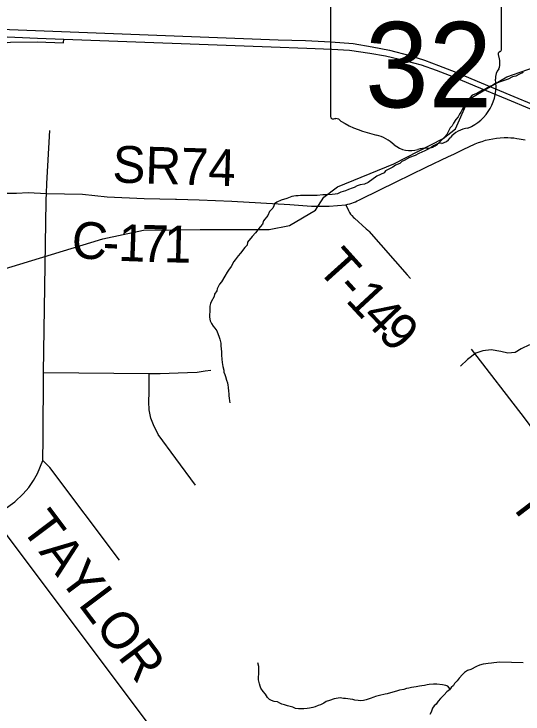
# Model space of a CAD drawing. Extents: x 0 to 34, y 0 to 22.
# Drawn here: x 3.321 to 4.106, y 16.889 to 17.969 of the extents above; entities that cross this region are included whole.
import ezdxf

# ---------------------------------------------------------------- set-up
doc = ezdxf.new("R2010")
doc.units = 0
for name, color, linetype in [('GM_X_County_Road', 7, 'Continuous'), ('GM_X_County_Road_Text', 7, 'Continuous'), ('GM_X_Interchange_Ramps', 7, 'Continuous'), ('GM_X_Minor_River', 7, 'Continuous'), ('GM_X_Rail_Line', 7, 'Continuous'), ('GM_X_State_Location', 7, 'Continuous'), ('GM_X_State_Route', 7, 'Continuous'), ('GM_X_State_Shield', 7, 'Continuous'), ('GM_X_Township_Road', 7, 'Continuous'), ('GM_X_Township_Road_Text', 7, 'Continuous')]:
    doc.layers.add(name, color=color, linetype=linetype)

msp = doc.modelspace()

# ---------------------------------------------------------------- linework, layer by layer
at = {"layer": 'GM_X_County_Road'}
for points in [[(4.0138, 17.7596), (4.032, 17.7682), (4.0373, 17.7704), (4.0428, 17.7723), (4.0483, 17.7739), (4.0539, 17.7753), (4.0595, 17.7764), (4.0652, 17.7772), (4.0709, 17.7778), (4.0767, 17.778), (4.0825, 17.7781), (4.0872, 17.7779), (4.092, 17.7775), (4.0967, 17.7769), (4.1001, 17.7764), (4.1034, 17.7758), (4.1092, 17.7745)], [(3.5715, 17.6829), (3.6063, 17.6822), (3.6566, 17.6798), (3.7464, 17.6747), (3.7797, 17.6723), (3.807, 17.6725), (3.8324, 17.6742), (3.8358, 17.6751), (3.8388, 17.6757), (3.8416, 17.6768), (3.8444, 17.6779), (3.8473, 17.6791), (3.8502, 17.6804), (3.8529, 17.6817), (3.8567, 17.6837), (3.9103, 17.7099), (3.9565, 17.7324), (3.991, 17.7487), (3.9993, 17.7527), (4.0138, 17.7596)], [(2.7634, 17.6374), (2.7985, 17.6331), (2.8242, 17.6342), (2.8636, 17.6377), (2.8914, 17.6399), (2.9314, 17.6429), (3.1876, 17.6772), (3.2242, 17.6821), (3.2631, 17.6869), (3.2961, 17.6924), (3.3246, 17.6924), (3.3425, 17.6933), (3.3709, 17.6917), (3.4263, 17.6906), (3.4641, 17.6869), (3.5212, 17.6842), (3.5695, 17.683), (3.5715, 17.6829)], [(3.7034, 16.6488), (3.5434, 16.8527), (3.3051, 17.1702), (3.2901, 17.1934)]]:
    msp.add_lwpolyline(points, dxfattribs=at)
at = {"layer": 'GM_X_Interchange_Ramps'}
msp.add_lwpolyline([(3.1029, 17.9047), (3.106, 17.9033), (3.1205, 17.8985), (3.1368, 17.8922), (3.1525, 17.8889), (3.167, 17.8879), (3.1832, 17.8902), (3.2012, 17.8958), (3.2205, 17.9034), (3.2348, 17.9089), (3.2473, 17.9137), (3.2605, 17.9165), (3.2756, 17.9199), (3.2939, 17.9235), (3.3149, 17.9256), (3.3561, 17.9261), (3.397, 17.9245), (3.3974, 17.93)], dxfattribs=at)
at = {"layer": 'GM_X_Minor_River'}
for points in [[(4.1062, 17.8785), (4.0997, 17.8756), (4.0951, 17.873), (4.0898, 17.8716), (4.0829, 17.8682), (4.0737, 17.8654), (4.0634, 17.8614), (4.0595, 17.8591), (4.0549, 17.8569), (4.0484, 17.8533), (4.0434, 17.8511), (4.0346, 17.8459), (4.0277, 17.8434), (4.0246, 17.84), (4.0223, 17.837), (4.0203, 17.8328), (4.0164, 17.8283), (4.0121, 17.8216), (4.0102, 17.8174), (4.0078, 17.8144), (4.0062, 17.8099), (4.0024, 17.8058), (3.9988, 17.8005), (3.9965, 17.796), (3.9938, 17.793), (3.9918, 17.7888)], [(3.9918, 17.7888), (3.9883, 17.7828), (3.9852, 17.7794), (3.9794, 17.7731), (3.9751, 17.769), (3.9678, 17.7653), (3.9644, 17.7627), (3.9575, 17.759), (3.9544, 17.7579), (3.9452, 17.7535), (3.9398, 17.7506), (3.931, 17.7473), (3.9226, 17.7425), (3.9191, 17.741), (3.9157, 17.7381), (3.9092, 17.7355), (3.9053, 17.7325), (3.9022, 17.7307), (3.8938, 17.7267), (3.8919, 17.7236), (3.8804, 17.7185), (3.8673, 17.7089), (3.8612, 17.7063), (3.8547, 17.7053), (3.8501, 17.7038), (3.8455, 17.7013), (3.8424, 17.6998), (3.8367, 17.698), (3.8321, 17.6958), (3.8248, 17.6936), (3.8195, 17.6914), (3.816, 17.6907), (3.8115, 17.6901), (3.8012, 17.6895), (3.797, 17.6896), (3.7882, 17.6889), (3.7841, 17.6886), (3.7746, 17.6888), (3.7628, 17.6886), (3.759, 17.6883), (3.7555, 17.688), (3.7494, 17.687), (3.7414, 17.6841), (3.733, 17.6815), (3.7261, 17.6786), (3.7223, 17.676), (3.7214, 17.6726), (3.7199, 17.6692), (3.7148, 17.664), (3.7121, 17.6579), (3.7055, 17.6497), (3.7042, 17.6444), (3.7004, 17.6403), (3.6934, 17.6309), (3.6883, 17.6253), (3.681, 17.6167), (3.6801, 17.6121), (3.6766, 17.6084), (3.67, 17.5997), (3.6662, 17.5956), (3.6619, 17.5896), (3.6595, 17.5866), (3.6556, 17.5791), (3.6513, 17.5734), (3.6494, 17.5704), (3.6459, 17.5644), (3.6408, 17.5557), (3.6377, 17.552), (3.6341, 17.5445), (3.6333, 17.5414), (3.6298, 17.5362), (3.6294, 17.5328), (3.6247, 17.5248), (3.6235, 17.5218), (3.6226, 17.5177), (3.6226, 17.5131), (3.6224, 17.5009), (3.6234, 17.4952), (3.6252, 17.491), (3.6278, 17.4871), (3.6304, 17.4841), (3.6334, 17.4798), (3.637, 17.4703), (3.6381, 17.4672), (3.6395, 17.4607), (3.6399, 17.4569), (3.6408, 17.4474), (3.6408, 17.4424), (3.641, 17.4363), (3.6417, 17.431), (3.6427, 17.4249), (3.6442, 17.4192), (3.6445, 17.4161), (3.646, 17.4123), (3.6467, 17.4092), (3.6485, 17.4039), (3.6499, 17.3997), (3.6506, 17.3959), (3.651, 17.3928), (3.6516, 17.386), (3.6519, 17.3829)], [(4.1161, 17.4582), (4.1034, 17.452), (4.0938, 17.4464), (4.0824, 17.4455), (4.0718, 17.448), (4.057, 17.4505), (4.044, 17.4488), (4.0333, 17.4452), (4.0202, 17.4355), (4.0098, 17.4251)], [(3.6519, 17.3829), (3.6522, 17.3795), (3.6526, 17.3757), (3.6529, 17.3719), (3.6536, 17.3688)], [(3.9934, 16.9269), (3.9899, 16.9314), (3.9869, 16.9326), (3.9816, 16.9334), (3.9732, 16.9343), (3.9679, 16.9344), (3.9611, 16.9338), (3.958, 16.9335), (3.9538, 16.9324), (3.95, 16.9321), (3.9462, 16.9314), (3.9409, 16.9303), (3.9374, 16.93), (3.934, 16.9293), (3.9298, 16.9282), (3.9264, 16.9279), (3.9222, 16.9265), (3.9153, 16.9251), (3.9107, 16.924), (3.9015, 16.9211), (3.8962, 16.9197), (3.8931, 16.919), (3.8847, 16.9172), (3.8786, 16.9155), (3.8756, 16.9147), (3.8702, 16.9126), (3.8641, 16.9104), (3.8599, 16.9093), (3.8557, 16.909), (3.8515, 16.9091), (3.8466, 16.9099), (3.8432, 16.9107), (3.8394, 16.9116), (3.8356, 16.912), (3.8322, 16.9125), (3.8292, 16.9125), (3.8239, 16.9134), (3.8147, 16.912), (3.8074, 16.9091), (3.8025, 16.9077), (3.7986, 16.9054), (3.7936, 16.9025), (3.7898, 16.9014), (3.7852, 16.8996), (3.7818, 16.8985), (3.7764, 16.8975), (3.773, 16.8968), (3.7677, 16.8965), (3.7593, 16.8966), (3.7551, 16.8971), (3.7506, 16.8991), (3.7468, 16.8999), (3.7427, 16.9011), (3.7378, 16.9027), (3.734, 16.9039), (3.7306, 16.9051), (3.7272, 16.9071), (3.7219, 16.9079), (3.7181, 16.9091), (3.7147, 16.9107), (3.7117, 16.9142), (3.7084, 16.9192), (3.705, 16.923), (3.7013, 16.9284), (3.7006, 16.9315), (3.6995, 16.9353), (3.6977, 16.941), (3.6978, 16.946), (3.6982, 16.9498), (3.6984, 16.9574), (3.6981, 16.9616), (3.6966, 16.9677)], [(4.1065, 16.9677), (4.07, 16.9684), (4.0609, 16.9674), (4.0574, 16.9671), (4.0525, 16.9664), (4.0487, 16.9661), (4.0445, 16.9654), (4.0387, 16.964), (4.0341, 16.9618), (4.0257, 16.957), (4.0204, 16.9556), (4.0157, 16.9526), (4.0127, 16.9496), (4.0076, 16.9436), (4.0045, 16.9399), (4.0002, 16.9354), (3.9987, 16.9324), (3.9952, 16.9294), (3.9925, 16.9256), (3.9886, 16.9227), (3.9844, 16.9182), (3.9786, 16.9122), (3.9751, 16.9081), (3.972, 16.9039), (3.9689, 16.901), (3.9665, 16.8976), (3.9642, 16.8915), (3.9622, 16.8878)]]:
    msp.add_lwpolyline(points, dxfattribs=at)
at = {"layer": 'GM_X_Rail_Line'}
msp.add_lwpolyline([(2.7988, 17.139), (2.7982, 17.2839), (2.8009, 17.3778), (2.8052, 17.4106), (2.8265, 17.4409), (2.8789, 17.4585), (2.9653, 17.4848), (3.2987, 17.5735), (3.4574, 17.6219), (3.5205, 17.6354), (3.6077, 17.6361), (3.7142, 17.6361), (3.7455, 17.6425), (3.7857, 17.6662), (3.7985, 17.6859), (3.8197, 17.7022), (3.9068, 17.7376), (3.9828, 17.7766), (4.0018, 17.7914), (4.0217, 17.8371), (4.0813, 17.8718), (4.1561, 17.8981)], dxfattribs=at)
at = {"layer": 'GM_X_State_Route'}
for points in [[(2.9371, 17.959), (3.1388, 17.9514), (3.2862, 17.946), (3.7281, 17.9289), (3.7702, 17.9281), (3.8093, 17.9259), (3.8437, 17.9232), (3.8731, 17.9182), (3.8998, 17.9129), (3.9312, 17.905), (3.954, 17.8978), (3.9754, 17.8895), (4.0024, 17.879), (4.0353, 17.8654), (4.0919, 17.8417)], [(3.0117, 17.9442), (3.1318, 17.9399), (3.2862, 17.9345), (3.3568, 17.9317), (3.3974, 17.93), (3.7174, 17.9183), (3.7724, 17.9161), (3.811, 17.9146), (3.838, 17.9128), (3.8696, 17.9086), (3.8937, 17.9045), (3.9244, 17.897), (3.9254, 17.8968)], [(3.9254, 17.8968), (3.949, 17.8902), (3.972, 17.8821), (3.999, 17.8716), (4.0319, 17.858), (4.0815, 17.8372)], [(4.0815, 17.8372), (4.1158, 17.8229), (4.1826, 17.7951), (4.2307, 17.7749), (4.2739, 17.7568), (4.3297, 17.7335), (4.3719, 17.7157), (4.421, 17.6953), (4.463, 17.6777), (4.5057, 17.6597), (4.5346, 17.6476), (4.5518, 17.6405)], [(4.0919, 17.8417), (4.1192, 17.8303), (4.1301, 17.8257), (4.1555, 17.8152), (4.1842, 17.8031), (4.2328, 17.7828), (4.275, 17.765), (4.3304, 17.7419), (4.3726, 17.7243), (4.4211, 17.7039), (4.4626, 17.6866), (4.5045, 17.6692), (4.5323, 17.6576), (4.5657, 17.6435), (4.5892, 17.6339), (4.6161, 17.6238), (4.6461, 17.6144), (4.6721, 17.6079), (4.691, 17.6039), (4.7099, 17.6008), (4.7264, 17.5985)]]:
    msp.add_lwpolyline(points, dxfattribs=at)
at = {"layer": 'GM_X_State_Shield'}
for p, q in [((3.8091, 18.0107), (3.8091, 17.8106)), ((4.0728, 17.9144), (4.0728, 18.0191)), ((4.0728, 17.9145), (4.0728, 17.9144))]:
    msp.add_line(p, q, dxfattribs=at)
for centre, radius, start, end in [((4.0697, 17.914), 0.00314, 289.6038, 7.7341), ((4.0721, 17.9067), 0.00454, 107.944, 210.337), ((4.0432, 17.8935), 0.0273, 340.033, 23.6496), ((4.0833, 17.8706), 0.0198, 136.8065, 186.9296), ((3.9945, 17.8573), 0.0699, 292.3089, 8.9858), ((3.8122, 17.8102), 0.00308, 171.9584, 258.3066), ((3.8127, 17.8306), 0.0235, 267.339, 280.6039), ((3.8175, 17.799), 0.00848, 29.7484, 93.2717), ((3.9245, 17.9788), 0.2019, 240.4129, 257.1985), ((4.024, 17.7544), 0.0383, 94.4031, 142.5768), ((3.8643, 17.7207), 0.0632, 47.1842, 75.836), ((3.9755, 17.7912), 0.0226, 282.8732, 323.2771), ((3.9327, 17.798), 0.0401, 230.7004, 286.2918), ((3.9558, 17.7289), 0.0329, 85.6951, 111.2099), ((3.9587, 17.7831), 0.0214, 268.777, 315.5493), ((3.9781, 17.7637), 0.00601, 65.7517, 132.6484)]:
    msp.add_arc(centre, radius, start, end, dxfattribs=at)
at = {"layer": 'GM_X_Township_Road'}
for points in [[(3.3701, 17.682), (3.3709, 17.6917), (3.3713, 17.707), (3.3756, 17.7892)], [(3.2901, 17.1934), (3.3055, 17.204), (3.322, 17.216), (3.3347, 17.2283), (3.3436, 17.2381), (3.3505, 17.2488), (3.3567, 17.2599), (3.3649, 17.2796), (3.3657, 17.3141), (3.366, 17.4153), (3.37, 17.6801), (3.3701, 17.682)], [(3.8324, 17.6742), (3.8368, 17.6654), (3.8382, 17.6626), (3.8399, 17.66), (3.8418, 17.6576), (3.8445, 17.6548), (3.846, 17.6535), (3.8641, 17.6375), (3.8664, 17.6354), (3.8682, 17.6335), (3.9275, 17.5662), (3.9322, 17.5607)], [(4.0259, 17.4517), (4.108, 17.3455), (4.1532, 17.2846), (4.171, 17.2597)], [(3.366, 17.4153), (3.5291, 17.4142), (3.546, 17.4139), (3.5741, 17.4149), (3.5882, 17.4153), (3.6034, 17.4163), (3.6157, 17.4181), (3.6241, 17.4191)], [(3.6005, 17.2419), (3.5705, 17.2828), (3.5431, 17.3197), (3.5358, 17.3346), (3.5318, 17.3449), (3.5289, 17.358), (3.5285, 17.3704), (3.5289, 17.385), (3.5291, 17.4142)], [(3.4835, 17.126), (3.3759, 17.269), (3.3649, 17.2796)]]:
    msp.add_lwpolyline(points, dxfattribs=at)

# ---------------------------------------------------------------- texts
at = {"layer": 'GM_X_County_Road_Text'}
for s, height, rotation, p in [('SR74', 0.05682, 358.1805, (3.4719, 17.709)), ('C', 0.0568, 354.9353, (3.4076, 17.5934)), ('1', 0.0568, 357.8945, (3.4806, 17.588)), ('7', 0.0568, 358.4194, (3.5161, 17.5867)), ('1', 0.0568, 358.5754, (3.5513, 17.5858)), ('-', 0.0568, 357.331, (3.4566, 17.5891)), ('TAYLOR', 0.05682, 306.9376, (3.3298, 17.1759))]:
    msp.add_text(s, height=height, rotation=rotation, dxfattribs=at).set_placement(p)
at = {"layer": 'GM_X_State_Location'}
for s in ['s', 'r']:
    msp.add_text(s, height=0.000189, dxfattribs=at).set_placement((3.938, 17.8973))
msp.add_text('32', height=0.000189, rotation=0, dxfattribs=at).set_placement((3.8903, 17.8836))
at = {"layer": 'GM_X_State_Shield'}
msp.add_text('32', height=0.13184, dxfattribs=at).set_placement((3.8623, 17.8247))
at = {"layer": 'GM_X_Township_Road_Text'}
for s, rotation, p in [('T', 312.0471, (3.7862, 17.5756)), ('-', 312.24, (3.8148, 17.5439)), ('1', 312.7907, (3.8309, 17.5262)), ('4', 313.5493, (3.8552, 17.4999)), ('9', 314.4351, (3.88, 17.4738)), ('T', 307.1709, (4.0831, 17.2144))]:
    msp.add_text(s, height=0.0568, rotation=rotation, dxfattribs=at).set_placement(p)

doc.saveas('drawing.dxf')
